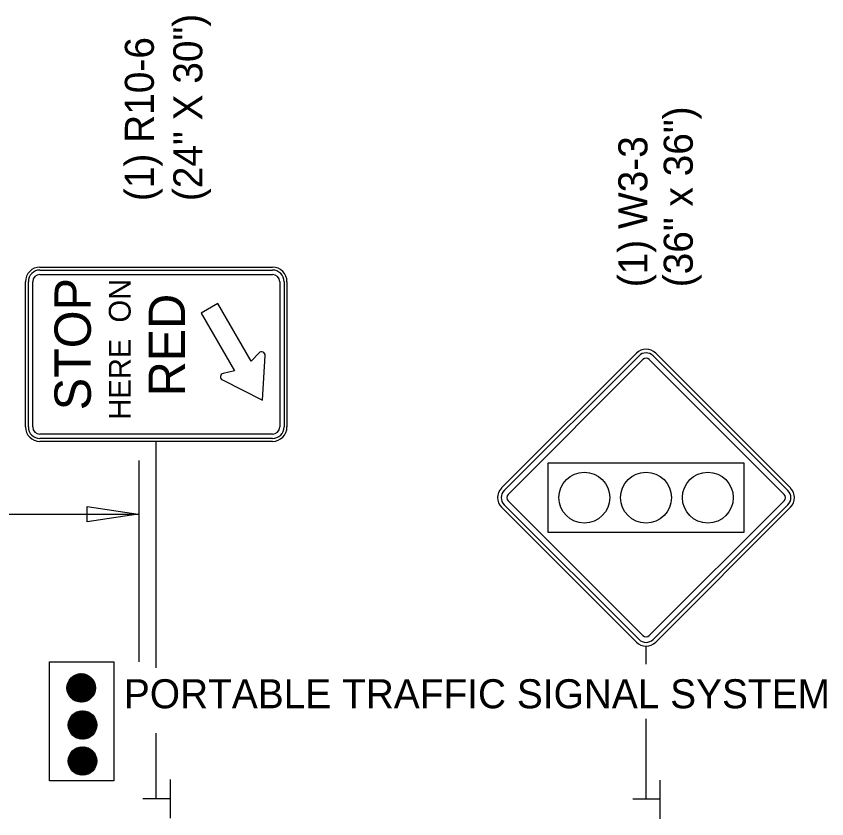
# Model space of a CAD drawing. Extents: x 1925873 to 1930787, y 596452 to 599617.
# Drawn here: x 1928053.1 to 1928220.4, y 596964 to 597129.8 of the extents above; entities that cross this region are included whole.
import ezdxf

# ---------------------------------------------------------------- set-up
doc = ezdxf.new("R2010")
doc.units = 0
for name, color, linetype in [('Default', 7, 'Continuous'), ('P_TC_Signs_Permanent', 7, 'Continuous'), ('R_Border', 7, 'Continuous')]:
    doc.layers.add(name, color=color, linetype=linetype)

msp = doc.modelspace()

# ---------------------------------------------------------------- linework, layer by layer
at = {"layer": 'Default'}
for p, q in [((1928078.38, 597037.96), (1928078.38, 596996.38)), ((1928067.72, 597025.34), (1928067.72, 597028.5)), ((1928067.72, 597028.5), (1928078.27, 597026.92)), ((1928014.71, 597026.92), (1928078.38, 597026.92)), ((1928078.27, 597026.92), (1928067.72, 597025.34)), ((1928063.54, 596991.07), (1928066.44, 596993.97)), ((1928063.54, 596990.89), (1928066.62, 596993.96)), ((1928063.55, 596991.26), (1928066.25, 596993.96)), ((1928063.56, 596990.72), (1928066.79, 596993.95)), ((1928063.57, 596991.46), (1928066.05, 596993.93)), ((1928063.58, 596990.56), (1928066.95, 596993.93)), ((1928063.61, 596990.41), (1928067.1, 596993.9)), ((1928063.61, 596991.68), (1928065.82, 596993.89)), ((1928063.64, 596990.26), (1928067.24, 596993.87)), ((1928063.68, 596990.12), (1928067.38, 596993.82)), ((1928063.68, 596991.93), (1928065.57, 596993.82)), ((1928063.73, 596989.99), (1928067.52, 596993.78)), ((1928063.78, 596989.86), (1928067.65, 596993.73)), ((1928063.8, 596992.23), (1928065.28, 596993.71)), ((1928063.84, 596989.74), (1928067.77, 596993.67)), ((1928063.9, 596989.62), (1928067.89, 596993.61)), ((1928063.96, 596989.5), (1928068, 596993.54)), ((1928064.01, 596992.63), (1928064.88, 596993.49)), ((1928064.03, 596989.39), (1928068.11, 596993.47)), ((1928064.11, 596989.28), (1928068.22, 596993.4)), ((1928064.19, 596989.18), (1928068.32, 596993.32)), ((1928064.27, 596989.08), (1928068.42, 596993.23)), ((1928064.36, 596988.99), (1928068.52, 596993.15)), ((1928064.45, 596988.9), (1928068.61, 596993.06)), ((1928064.54, 596988.81), (1928068.69, 596992.96)), ((1928064.64, 596988.73), (1928068.78, 596992.87)), ((1928064.74, 596988.65), (1928068.85, 596992.76)), ((1928064.85, 596988.58), (1928068.93, 596992.66)), ((1928064.96, 596988.51), (1928069, 596992.55)), ((1928065.07, 596988.44), (1928069.06, 596992.43)), ((1928065.19, 596988.38), (1928069.13, 596992.31)), ((1928065.32, 596988.32), (1928069.18, 596992.19)), ((1928065.45, 596988.27), (1928069.24, 596992.06)), ((1928065.58, 596988.22), (1928069.28, 596991.92)), ((1928065.72, 596988.18), (1928069.32, 596991.78)), ((1928065.87, 596988.15), (1928069.36, 596991.64)), ((1928066.02, 596988.12), (1928069.39, 596991.49)), ((1928066.18, 596988.1), (1928069.41, 596991.33)), ((1928066.35, 596988.09), (1928069.42, 596991.16)), ((1928066.53, 596988.08), (1928069.42, 596990.98)), ((1928066.72, 596988.09), (1928069.41, 596990.79)), ((1928066.92, 596988.12), (1928069.39, 596990.59)), ((1928067.14, 596988.16), (1928069.35, 596990.36)), ((1928067.39, 596988.23), (1928069.28, 596990.11)), ((1928067.69, 596988.34), (1928069.16, 596989.82)), ((1928068.09, 596988.56), (1928068.95, 596989.42)), ((1928063.81, 596983.41), (1928066.71, 596986.31)), ((1928063.81, 596983.23), (1928066.89, 596986.3)), ((1928063.82, 596983.6), (1928066.52, 596986.3)), ((1928063.82, 596983.06), (1928067.05, 596986.29)), ((1928063.84, 596983.8), (1928066.31, 596986.27)), ((1928063.85, 596982.9), (1928067.21, 596986.27)), ((1928063.87, 596982.75), (1928067.37, 596986.24)), ((1928063.88, 596984.02), (1928066.09, 596986.23)), ((1928063.91, 596982.6), (1928067.51, 596986.21)), ((1928063.95, 596982.46), (1928067.65, 596986.16)), ((1928063.95, 596984.27), (1928065.84, 596986.16)), ((1928064, 596982.33), (1928067.79, 596986.12)), ((1928064.05, 596982.2), (1928067.92, 596986.07)), ((1928064.07, 596984.57), (1928065.55, 596986.05)), ((1928064.11, 596982.08), (1928068.04, 596986.01)), ((1928064.17, 596981.96), (1928068.16, 596985.95)), ((1928064.23, 596981.84), (1928068.27, 596985.88)), ((1928064.28, 596984.97), (1928065.15, 596985.83)), ((1928064.3, 596981.73), (1928068.38, 596985.81)), ((1928064.38, 596981.62), (1928068.49, 596985.74)), ((1928064.46, 596981.52), (1928068.59, 596985.66)), ((1928064.54, 596981.42), (1928068.69, 596985.58)), ((1928064.63, 596981.33), (1928068.79, 596985.49)), ((1928064.72, 596981.24), (1928068.88, 596985.4)), ((1928064.81, 596981.15), (1928068.96, 596985.3)), ((1928064.91, 596981.07), (1928069.05, 596985.21)), ((1928065.01, 596980.99), (1928069.12, 596985.1)), ((1928065.12, 596980.92), (1928069.2, 596985)), ((1928065.23, 596980.85), (1928069.27, 596984.89)), ((1928065.34, 596980.78), (1928069.33, 596984.77)), ((1928065.46, 596980.72), (1928069.4, 596984.65)), ((1928065.59, 596980.66), (1928069.45, 596984.53)), ((1928065.72, 596980.61), (1928069.5, 596984.4)), ((1928065.85, 596980.56), (1928069.55, 596984.27)), ((1928065.99, 596980.52), (1928069.59, 596984.13)), ((1928066.14, 596980.49), (1928069.63, 596983.98)), ((1928066.29, 596980.46), (1928069.66, 596983.83)), ((1928066.45, 596980.44), (1928069.68, 596983.67)), ((1928066.62, 596980.43), (1928069.69, 596983.5)), ((1928066.79, 596980.42), (1928069.69, 596983.32)), ((1928066.98, 596980.43), (1928069.68, 596983.13)), ((1928067.19, 596980.46), (1928069.66, 596982.93)), ((1928067.41, 596980.5), (1928069.62, 596982.7)), ((1928067.66, 596980.57), (1928069.55, 596982.45)), ((1928067.96, 596980.68), (1928069.43, 596982.16)), ((1928068.36, 596980.9), (1928069.22, 596981.76)), ((1928063.81, 596975.89), (1928066.79, 596978.87)), ((1928063.81, 596976.07), (1928066.6, 596978.86)), ((1928063.82, 596975.71), (1928066.96, 596978.86)), ((1928063.83, 596976.27), (1928066.41, 596978.85)), ((1928063.83, 596975.55), (1928067.13, 596978.84)), ((1928063.86, 596975.39), (1928067.28, 596978.82)), ((1928063.86, 596976.48), (1928066.19, 596978.81)), ((1928063.89, 596975.24), (1928067.43, 596978.79)), ((1928063.92, 596976.72), (1928065.96, 596978.76)), ((1928063.93, 596975.1), (1928067.58, 596978.75)), ((1928063.97, 596974.96), (1928067.71, 596978.71)), ((1928064.01, 596976.99), (1928065.68, 596978.67)), ((1928064.02, 596974.83), (1928067.84, 596978.66)), ((1928064.07, 596974.71), (1928067.97, 596978.6)), ((1928064.13, 596974.58), (1928068.09, 596978.54)), ((1928064.17, 596977.33), (1928065.35, 596978.51)), ((1928064.2, 596974.47), (1928068.21, 596978.48)), ((1928064.26, 596974.35), (1928068.32, 596978.41)), ((1928064.34, 596974.24), (1928068.43, 596978.34)), ((1928064.41, 596974.14), (1928068.54, 596978.26)), ((1928064.49, 596974.04), (1928068.64, 596978.18)), ((1928064.58, 596973.94), (1928068.73, 596978.1)), ((1928064.67, 596973.85), (1928068.83, 596978.01)), ((1928064.76, 596973.76), (1928068.91, 596977.92)), ((1928064.85, 596973.68), (1928069, 596977.82)), ((1928064.95, 596973.6), (1928069.08, 596977.72)), ((1928065.06, 596973.52), (1928069.16, 596977.62)), ((1928065.17, 596973.45), (1928069.23, 596977.51)), ((1928065.28, 596973.38), (1928069.3, 596977.4)), ((1928065.4, 596973.31), (1928069.36, 596977.28)), ((1928065.52, 596973.25), (1928069.42, 596977.16)), ((1928065.64, 596973.2), (1928069.48, 596977.03)), ((1928065.78, 596973.15), (1928069.53, 596976.9)), ((1928065.91, 596973.11), (1928069.57, 596976.76)), ((1928066.05, 596973.07), (1928069.61, 596976.62)), ((1928066.2, 596973.04), (1928069.64, 596976.47)), ((1928066.36, 596973.01), (1928069.67, 596976.32)), ((1928066.52, 596972.99), (1928069.68, 596976.15)), ((1928066.69, 596972.98), (1928069.69, 596975.98)), ((1928066.88, 596972.99), (1928069.69, 596975.8)), ((1928067.07, 596973), (1928069.67, 596975.6)), ((1928067.29, 596973.03), (1928069.64, 596975.39)), ((1928067.52, 596973.09), (1928069.59, 596975.16)), ((1928067.79, 596973.17), (1928069.5, 596974.89)), ((1928068.11, 596973.32), (1928069.36, 596974.56)), ((1928068.69, 596973.71), (1928068.97, 596973.99)), ((1928084.81, 596972.09), (1928084.81, 596964.09)), ((1928185.95, 596971.99), (1928185.95, 596963.98)), ((1928084.69, 596968.11), (1928079.22, 596968.11)), ((1928185.83, 596968.01), (1928180.37, 596968.01))]:
    msp.add_line(p, q, dxfattribs=at)
msp.add_lwpolyline([(1928059.91, 596996.38), (1928073.2, 596996.38), (1928073.2, 596971.84), (1928059.91, 596971.84)], close=True, dxfattribs=at)
for centre in [(1928066.48, 596991.02), (1928066.75, 596983.36), (1928066.75, 596975.93)]:
    msp.add_circle(centre, 2.94, dxfattribs=at)
at = {"layer": 'P_TC_Signs_Permanent'}
for p, q in [((1928057.96, 597077.92), (1928105.96, 597077.92)), ((1928057.96, 597077.32), (1928105.96, 597077.32)), ((1928057.96, 597076.42), (1928105.96, 597076.42)), ((1928054.96, 597044.92), (1928054.96, 597074.92)), ((1928055.56, 597044.92), (1928055.56, 597074.92)), ((1928056.46, 597044.92), (1928056.46, 597074.92)), ((1928107.46, 597074.92), (1928107.46, 597044.92)), ((1928108.36, 597074.92), (1928108.36, 597044.92)), ((1928108.96, 597074.92), (1928108.96, 597044.92)), ((1928153.27, 597032.31), (1928181.11, 597060.15)), ((1928185.09, 597060.15), (1928212.93, 597032.31)), ((1928153.8, 597031.78), (1928181.64, 597059.62)), ((1928182.44, 597058.83), (1928154.6, 597030.98)), ((1928211.61, 597030.98), (1928183.76, 597058.83)), ((1928184.56, 597059.62), (1928212.4, 597031.78)), ((1928105.96, 597043.42), (1928057.96, 597043.42)), ((1928105.96, 597042.52), (1928057.96, 597042.52)), ((1928105.96, 597041.92), (1928057.96, 597041.92)), ((1928181.11, 597000.49), (1928153.27, 597028.33)), ((1928181.64, 597001.02), (1928153.8, 597028.86)), ((1928154.6, 597029.66), (1928182.44, 597001.82)), ((1928183.76, 597001.82), (1928211.61, 597029.66)), ((1928212.4, 597028.86), (1928184.56, 597001.02)), ((1928212.93, 597028.33), (1928185.09, 597000.49))]:
    msp.add_line(p, q, dxfattribs=at)
for points in [[(1928103.21, 597060.23), (1928101.56, 597058.48), (1928094.68, 597070.4), (1928091.27, 597068.44), (1928098.15, 597056.51), (1928095.78, 597055.96)], [(1928095.62, 597054.62), (1928103.94, 597050.42), (1928104.45, 597059.69)]]:
    msp.add_lwpolyline(points, dxfattribs=at)
msp.add_lwpolyline([(1928203.35, 597023.2), (1928203.35, 597037.45), (1928162.85, 597037.45), (1928162.85, 597023.2)], close=True, dxfattribs=at)
for centre in [(1928170.35, 597030.32), (1928183.1, 597030.32), (1928195.85, 597030.32)]:
    msp.add_circle(centre, 5.25, dxfattribs=at)
for centre, radius, start, end in [((1928057.96, 597074.92), 3, 90, 180), ((1928057.96, 597074.92), 2.4, 90, 180), ((1928105.96, 597074.92), 3, 360, 90), ((1928105.96, 597074.92), 2.4, 360, 90), ((1928057.96, 597074.92), 1.5, 90, 180), ((1928105.96, 597074.92), 1.5, 360, 90), ((1928103.73, 597059.73), 0.72, 356.857, 136.6377), ((1928183.1, 597058.16), 2.81, 45, 135), ((1928183.1, 597058.16), 2.06, 45, 135), ((1928183.1, 597058.16), 0.938, 45, 135), ((1928095.94, 597055.26), 0.72, 103.0349, 243.2286), ((1928057.96, 597044.92), 3, 180, 270), ((1928057.96, 597044.92), 2.4, 180, 270), ((1928057.96, 597044.92), 1.5, 180, 270), ((1928105.96, 597044.92), 3, 270, 360), ((1928105.96, 597044.92), 2.4, 270, 360), ((1928105.96, 597044.92), 1.5, 270, 360), ((1928155.26, 597030.32), 2.81, 135, 225), ((1928155.26, 597030.32), 2.06, 135, 225), ((1928210.94, 597030.32), 2.06, 315, 45), ((1928210.94, 597030.32), 2.81, 315, 45), ((1928155.26, 597030.32), 0.938, 135, 225), ((1928210.94, 597030.32), 0.938, 315, 45), ((1928183.1, 597002.48), 0.938, 225, 315), ((1928183.1, 597002.48), 2.81, 225, 315), ((1928183.1, 597002.48), 2.06, 225, 315)]:
    msp.add_arc(centre, radius, start, end, dxfattribs=at)
at = {"layer": 'R_Border'}
for p, q in [((1928081.96, 596995.17), (1928081.96, 597041.92)), ((1928183.1, 596995.9), (1928183.1, 596999.67)), ((1928183.1, 596968.01), (1928183.1, 596984.63)), ((1928081.96, 596968.11), (1928081.96, 596981.64))]:
    msp.add_line(p, q, dxfattribs=at)

# ---------------------------------------------------------------- texts
at = {"layer": 'Default'}
msp.add_text('PORTABLE TRAFFIC SIGNAL SYSTEM', height=5.9996, rotation=360, dxfattribs=at).set_placement((1928075.29, 596986.81))
at = {"layer": 'P_TC_Signs_Permanent'}
for s, height, p in [('STOP', 7.5, (1928068.46, 597048.36)), ('HERE  ON', 4.5, (1928076.68, 597046.42)), ('RED', 7.5, (1928087.9, 597051.25))]:
    msp.add_text(s, height=height, rotation=90, dxfattribs=at).set_placement(p)
at = {"layer": 'R_Border'}
for s, height, p in [('(24" X 30")', 5.9996, (1928091.49, 597091.56)), ('(1) R10-6', 6, (1928081.48, 597091.56)), ('(36" x 36")', 5.9996, (1928192.74, 597073.77)), ('(1) W3-3', 6, (1928183.38, 597073.77))]:
    msp.add_text(s, height=height, rotation=90, dxfattribs=at).set_placement(p)

doc.saveas('drawing.dxf')
